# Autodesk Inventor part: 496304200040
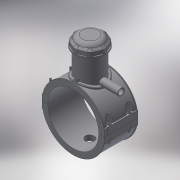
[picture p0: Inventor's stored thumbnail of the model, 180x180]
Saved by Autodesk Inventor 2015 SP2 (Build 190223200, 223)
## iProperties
Created: 2017-07
Part Number: 496304200040
Material: Generic
Description: PLASSON TAPPING SADDLE 200x40
Document SubType Name: Modeling
Designer: KIM
Mass: 1299.29 g
Surface Area: 3129.51 cm^2
Volume: 1299.29 cm^3
Density: 1 g/cm^3
Appearance: Default
Author: KIM
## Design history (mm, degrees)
derived "496304.ipt"
feature "Solid1::496304.ipt"
feature "Solid2::496304.ipt"
feature "Solid4::496304.ipt"
feature "Solid5::496304.ipt"
tag "TaggingFeature1" dims "B_" = 202
body "Solid1"
body "Solid2"
other parameters: "L_" = 176, "d_t" = 6, "H_2" = 177, "H_" = 142, "d1" = 228, "d148" = 3, "d160" = 3, "d169" = 3, "d192" = 5.6, "d2" = 262.6, "d4" = 176, "d5" = 0, "d6" = 0.1, "d8" = 0, "d19" = 6, "d20" = 6, "d21" = 105.6, "d23" = 0, "d24" = 52.8, "d26" = 0, "d29" = 3, "d30" = 66.66667, "d31" = 6, "d32" = 0, "d33" = 0, "d34" = 0.6, "d40" = 118.56, "d43" = 0, "d45" = 0, "d47" = 219.6, "d70" = 15, "d72" = 0, "d73" = 6, "d75" = 5, "d76" = 0, "d79" = 15, "d80" = 70.4, "d82" = 5 deg, "d84" = 4, "d85" = 14, "d86" = 0, "d87" = 3, "d88" = 0, "d89" = 1, "d90" = 1, "d91" = 140.8, "d92" = 0, "d93" = 0.5, "d94" = 105.26316, "d96" = 232.56, "d97" = 3.52, "d98" = 0, "d102" = 2, "d120" = 140 deg, "d121" = 24.228, "d122" = 20 deg, "d123" = 456, "d124" = 136.8, "d126" = 0, "d143" = 206, "d145" = 21.53846, "d149" = 3, "d150" = 23.69231, "d153" = 176, "d154" = 0, "d156" = 114, "d157" = 160 deg, "d159" = 5.6, "d161" = 3, "d162" = 105.6, "d163" = 0, "d168" = 111.21951, "d170" = 3, "d172" = 0, "d173" = 1, "d176" = 20 deg, "d177" = 14, "d178" = 28, "d180" = 0, "d183" = 11.2, "d184" = 11.2, "d185" = 57.2, "d186" = 57.2, "d187" = 114, "d188" = 8.4, "d189" = 14, "d190" = 0, "d191" = 171, "d193" = 5.6, "d194" = 6.16, "d195" = 90 deg, "d197" = 0, "d199" = 0, "d200" = 14, "d202" = 0, "d203" = 177, "d204" = 76, "d205" = 56, "d206" = 68, "d207" = 132.75, "d208" = 138.06, "d209" = 164.61, "d210" = 68.8, "d212" = 64, "d213" = 36, "d216" = 0, "d219" = 4, "d224" = 0, "d230" = 4, "d233" = 6, "d236" = 101, "d237" = 52.8, "d238" = 6.02433, "d240" = 52.8, "d241" = 52.8, "d242" = 52.8, "d243" = 6, "d244" = 52.8, "d245" = 52.8, "d246" = 52.8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
